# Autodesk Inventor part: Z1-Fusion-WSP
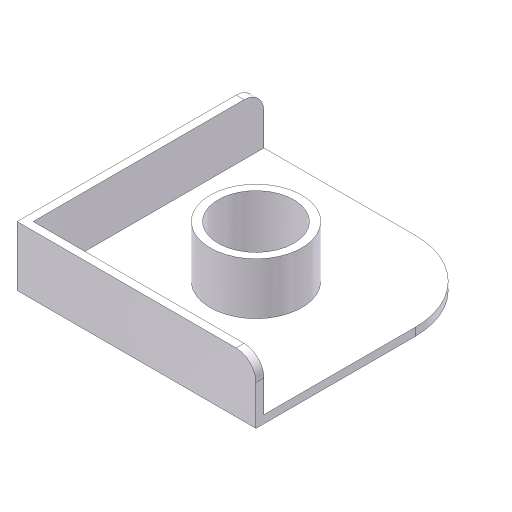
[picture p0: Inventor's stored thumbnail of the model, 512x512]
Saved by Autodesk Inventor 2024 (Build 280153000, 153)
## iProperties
Created: 2023-03
Part Number: Z1-Fusion-WSP
Document SubType Name: Modeling
Designer: Andrzej Jaskulski
Material: Kurs-AJ
Density: 1 g/cm^3
Mass: 11.2231 g
Surface Area: 118.487 cm^2
Volume: 11.2231 cm^3
Appearance: Kurs-AJ
Checked By: A.J.
Engr Approved By: Andrzej Jaskulski
Mfg Approved By: Andrzej Jaskulski
Authority: A.J.
Company: ATC
Shininess: 21.0
Length Units: 11269
Angle Units: 11279
Time Units: 11290
Mass Units: 11283
Length Display Precision: 3
Angle Display Precision: 2
Compacted: True
Density: 0.0
Volumn: 0.0
Area: 0.0
PropertySet Name: Model Information
Control State: 0
Master: False
Checked Out: False
Title: A.J.: Kurs R2024-MEP
Author: Andrzej Jaskulski
Revision Number: 1/24
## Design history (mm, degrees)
sketch "Sketch1"
  geometry: L1 (0, 0)-(60, 0); L2 (60, 0)-(60, 60); L3 (60, 60)-(0, 60); L4 (0, 60)-(0, 0)
  constraints: 8 end point, 2 parallel, 1 horizontal, 1 perpendicular, 1 other
  dimensions: "d0" = 60 distance of L1.start L1.end (= x); "d1" = 60 distance of L1.end L2.end (= y)
extrude "Baza" new body sketch "Sketch1" distance "d2" = 15 (= h); taper "d3" = 0 deg
sketch "Sketch3"
  geometry: L1 (0, 0)-(0, 60) reference; L2 (60, 0)-(0, 0) reference; 1 further point
  dimensions: "d9" = 30 distance from line of L1 point (30, 30) (= Lx); "d10" = 30 distance from line of L2 point (30, 30) (= Ly)
hole "Otwór" sketch "Sketch3" diameter "d7" = 19; stored, may be unused: countersink angle "d18" = 60 deg, drill point angle "d20" = 118 deg; dims "d8" = 6, "d16" = 4, "d17" = 2, "d19" = 8
fillet "Zaokrąglenie1" dims "d4" = 20 (= d)
fillet "Zaokrąglenie2" dims "d5" = 5 (= 0.5 x r)
feature "Skorupa1" dims "d6" = 2
node "Bryła1"
node "Korpusy bryłowe"
node "Korpusy powierzchniowe"
other parameters: "x" = 60 [user parameter; used in 1 equation term], "y" = 60 [user parameter; used in 1 equation term], "h" = 15 [user parameter; used in 1 equation term], "Lx" = 30 [user parameter; used in 1 equation term], "Ly" = 30 [user parameter; used in 1 equation term], "L2" = 1 [user parameter]
